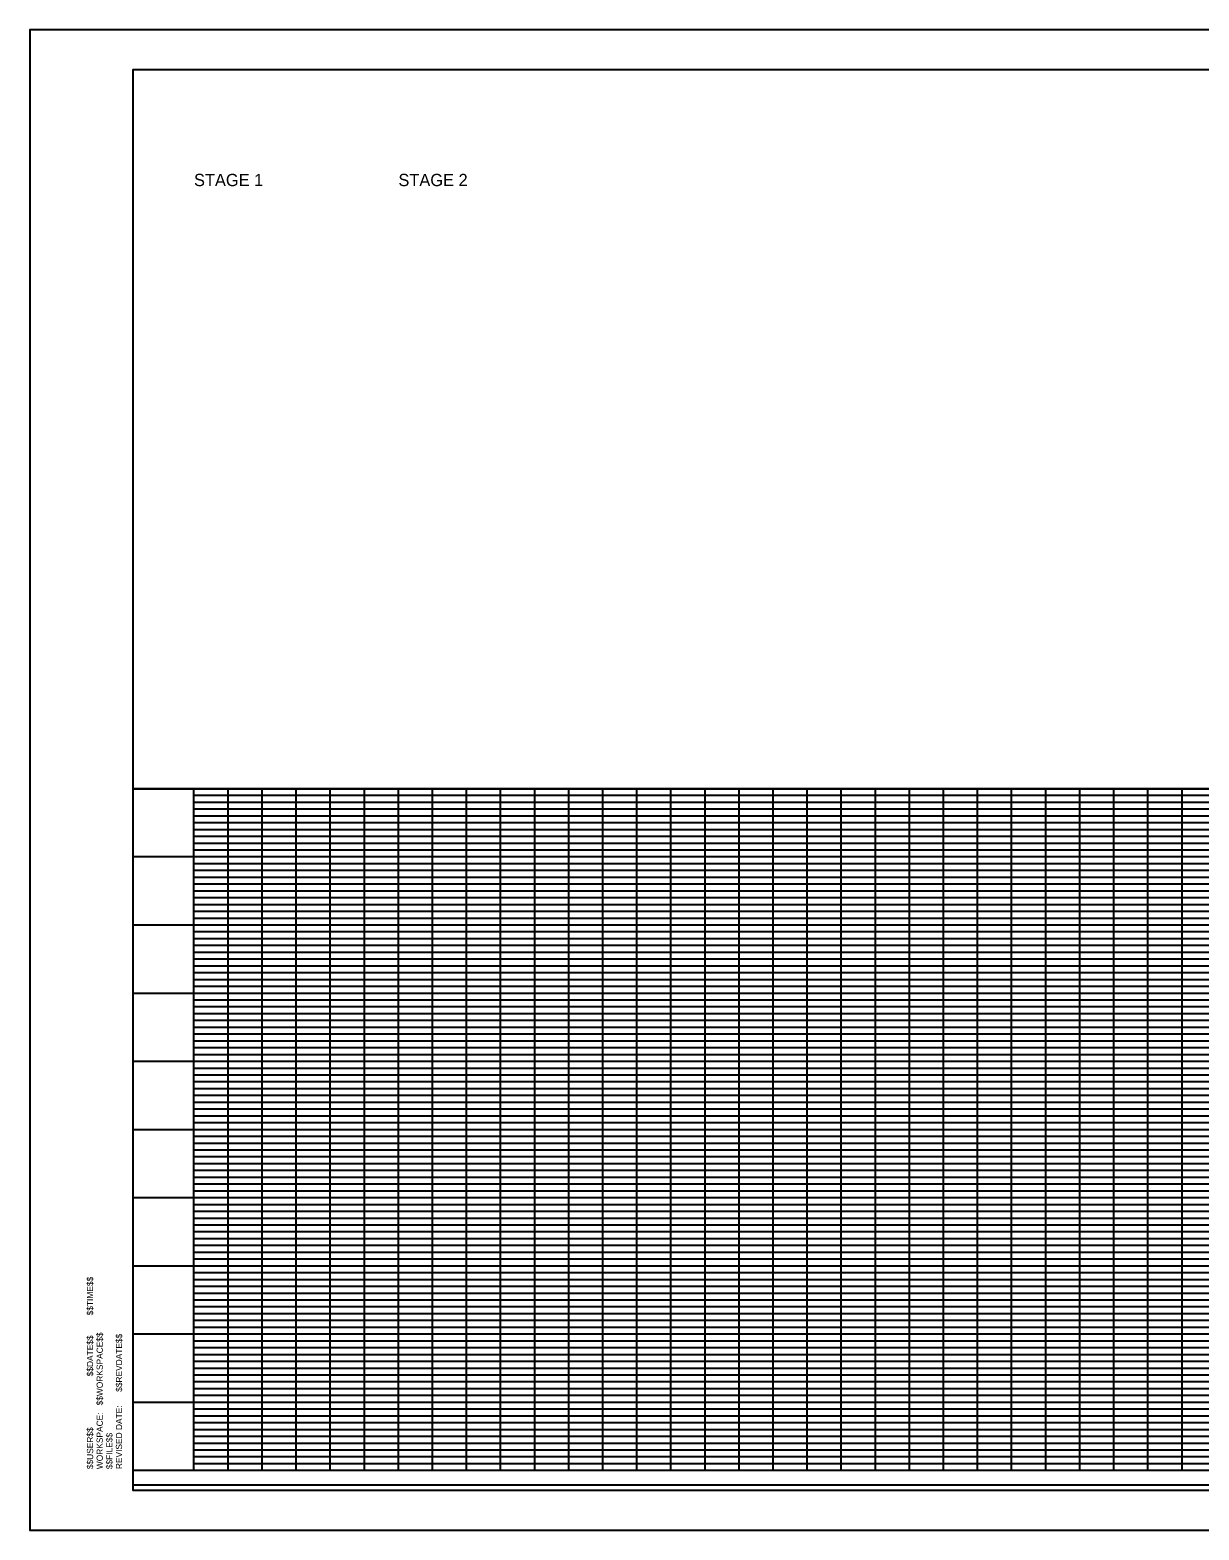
# Model space of a CAD drawing. Extents: x 0 to 1228740, y 0 to 152440.
# Drawn here: x 0 to 17.16, y 0 to 22 of the extents above; entities that cross this region are included whole.
import ezdxf

# ---------------------------------------------------------------- set-up
doc = ezdxf.new("R2010")
doc.units = 0
for name, color, linetype in [('G-TBLK', 7, 'Continuous'), ('R_Border', 7, 'Continuous'), ('R_Grid', 7, 'Continuous'), ('R_No Plot', 7, 'Continuous'), ('R_XS_EARTHWORK_STAGE1', 7, 'Continuous'), ('R_XS_EARTHWORK_STAGE2', 7, 'Continuous')]:
    doc.layers.add(name, color=color, linetype=linetype)

msp = doc.modelspace()

# ---------------------------------------------------------------- linework, layer by layer
at = {"layer": 'R_Border'}
for p, q in [((1.516, 21.423), (33.423, 21.423)), ((1.516, 0.577), (1.516, 21.423)), ((33.423, 0.577), (1.516, 0.577))]:
    msp.add_line(p, q, dxfattribs=at)
msp.add_lwpolyline([(34, 22), (0, 22), (0, 0), (34, 0)], close=True, dxfattribs=at)
at = {"layer": 'R_Grid'}
for p, q in [((33.423, 10.871), (1.516, 10.871)), ((2.407, 0.871), (2.407, 10.871)), ((2.907, 0.871), (2.907, 10.871)), ((3.407, 0.871), (3.407, 10.871)), ((3.907, 0.871), (3.907, 10.871)), ((4.407, 0.871), (4.407, 10.871)), ((4.907, 0.871), (4.907, 10.871)), ((5.407, 0.871), (5.407, 10.871)), ((5.907, 0.871), (5.907, 10.871)), ((6.407, 0.871), (6.407, 10.871)), ((6.907, 0.871), (6.907, 10.871)), ((7.407, 0.871), (7.407, 10.871)), ((7.907, 0.871), (7.907, 10.871)), ((8.407, 0.871), (8.407, 10.871)), ((8.907, 0.871), (8.907, 10.871)), ((9.407, 0.871), (9.407, 10.871)), ((9.907, 0.871), (9.907, 10.871)), ((10.407, 0.871), (10.407, 10.871)), ((10.907, 0.871), (10.907, 10.871)), ((11.407, 0.871), (11.407, 10.871)), ((11.907, 0.871), (11.907, 10.871)), ((12.407, 0.871), (12.407, 10.871)), ((12.907, 0.871), (12.907, 10.871)), ((13.407, 0.871), (13.407, 10.871)), ((13.907, 0.871), (13.907, 10.871)), ((14.407, 0.871), (14.407, 10.871)), ((14.907, 0.871), (14.907, 10.871)), ((15.407, 0.871), (15.407, 10.871)), ((15.907, 0.871), (15.907, 10.871)), ((16.407, 0.871), (16.407, 10.871)), ((16.907, 0.871), (16.907, 10.871)), ((32.407, 10.771), (2.407, 10.771)), ((32.407, 10.671), (2.407, 10.671)), ((32.407, 10.571), (2.407, 10.571)), ((32.407, 10.471), (2.407, 10.471)), ((32.407, 10.371), (2.407, 10.371)), ((32.407, 10.271), (2.407, 10.271)), ((32.407, 10.171), (2.407, 10.171)), ((32.407, 10.071), (2.407, 10.071)), ((32.407, 9.971), (2.407, 9.971)), ((33.423, 9.871), (1.516, 9.871)), ((32.407, 9.771), (2.407, 9.771)), ((32.407, 9.671), (2.407, 9.671)), ((32.407, 9.571), (2.407, 9.571)), ((32.407, 9.471), (2.407, 9.471)), ((32.407, 9.371), (2.407, 9.371)), ((32.407, 9.271), (2.407, 9.271)), ((32.407, 9.171), (2.407, 9.171)), ((32.407, 9.071), (2.407, 9.071)), ((33.423, 8.871), (1.516, 8.871)), ((32.407, 8.971), (2.407, 8.971)), ((32.407, 8.771), (2.407, 8.771)), ((32.407, 8.671), (2.407, 8.671)), ((32.407, 8.571), (2.407, 8.571)), ((32.407, 8.471), (2.407, 8.471)), ((32.407, 8.371), (2.407, 8.371)), ((32.407, 8.271), (2.407, 8.271)), ((32.407, 8.171), (2.407, 8.171)), ((32.407, 8.071), (2.407, 8.071)), ((32.407, 7.971), (2.407, 7.971)), ((33.423, 7.871), (1.516, 7.871)), ((32.407, 7.771), (2.407, 7.771)), ((32.407, 7.671), (2.407, 7.671)), ((32.407, 7.571), (2.407, 7.571)), ((32.407, 7.471), (2.407, 7.471)), ((32.407, 7.371), (2.407, 7.371)), ((32.407, 7.271), (2.407, 7.271)), ((32.407, 7.171), (2.407, 7.171)), ((32.407, 7.071), (2.407, 7.071)), ((33.423, 6.871), (1.516, 6.871)), ((32.407, 6.971), (2.407, 6.971)), ((32.407, 6.771), (2.407, 6.771)), ((32.407, 6.671), (2.407, 6.671)), ((32.407, 6.571), (2.407, 6.571)), ((32.407, 6.471), (2.407, 6.471)), ((32.407, 6.371), (2.407, 6.371)), ((32.407, 6.271), (2.407, 6.271)), ((32.407, 6.171), (2.407, 6.171)), ((32.407, 6.071), (2.407, 6.071)), ((32.407, 5.971), (2.407, 5.971)), ((33.423, 5.871), (1.516, 5.871)), ((32.407, 5.771), (2.407, 5.771)), ((32.407, 5.671), (2.407, 5.671)), ((32.407, 5.571), (2.407, 5.571)), ((32.407, 5.471), (2.407, 5.471)), ((32.407, 5.371), (2.407, 5.371)), ((32.407, 5.271), (2.407, 5.271)), ((32.407, 5.171), (2.407, 5.171)), ((32.407, 5.071), (2.407, 5.071)), ((33.423, 4.871), (1.516, 4.871)), ((32.407, 4.971), (2.407, 4.971)), ((32.407, 4.771), (2.407, 4.771)), ((32.407, 4.671), (2.407, 4.671)), ((32.407, 4.571), (2.407, 4.571)), ((32.407, 4.471), (2.407, 4.471)), ((32.407, 4.371), (2.407, 4.371)), ((32.407, 4.271), (2.407, 4.271)), ((32.407, 4.171), (2.407, 4.171)), ((32.407, 4.071), (2.407, 4.071)), ((32.407, 3.971), (2.407, 3.971)), ((33.423, 3.871), (1.516, 3.871)), ((32.407, 3.771), (2.407, 3.771)), ((32.407, 3.671), (2.407, 3.671)), ((32.407, 3.571), (2.407, 3.571)), ((32.407, 3.471), (2.407, 3.471)), ((32.407, 3.371), (2.407, 3.371)), ((32.407, 3.271), (2.407, 3.271)), ((32.407, 3.171), (2.407, 3.171)), ((33.423, 2.871), (1.516, 2.871)), ((32.407, 3.071), (2.407, 3.071)), ((32.407, 2.971), (2.407, 2.971)), ((32.407, 2.771), (2.407, 2.771)), ((32.407, 2.671), (2.407, 2.671)), ((32.407, 2.571), (2.407, 2.571)), ((32.407, 2.471), (2.407, 2.471)), ((32.407, 2.371), (2.407, 2.371)), ((32.407, 2.271), (2.407, 2.271)), ((32.407, 2.171), (2.407, 2.171)), ((32.407, 2.071), (2.407, 2.071)), ((33.423, 1.871), (1.516, 1.871)), ((32.407, 1.971), (2.407, 1.971)), ((32.407, 1.771), (2.407, 1.771)), ((32.407, 1.671), (2.407, 1.671)), ((32.407, 1.571), (2.407, 1.571)), ((32.407, 1.471), (2.407, 1.471)), ((32.407, 1.371), (2.407, 1.371)), ((32.407, 1.271), (2.407, 1.271)), ((32.407, 1.171), (2.407, 1.171)), ((32.407, 1.071), (2.407, 1.071)), ((32.407, 0.971), (2.407, 0.971)), ((33.423, 0.871), (1.516, 0.871))]:
    msp.add_line(p, q, dxfattribs=at)
at = {"layer": 'R_No Plot'}
for points in [[(33.423, 17.405), (33.423, 10.871), (1.516, 10.871), (1.516, 21.423), (25.197, 21.423), (25.197, 20.435), (28.749, 20.435), (28.749, 20.078), (29.113, 20.078), (29.113, 20.143), (30.667, 20.143)], [(33.423, 17.405), (33.423, 0.657), (1.516, 0.657), (1.516, 21.423), (25.197, 21.423), (25.197, 20.435), (28.749, 20.435), (28.749, 20.078), (29.113, 20.078), (29.113, 20.143), (30.667, 20.143)]]:
    msp.add_lwpolyline(points, dxfattribs=at)
msp.add_lwpolyline([(1.516, 10.871), (33.423, 10.871), (33.423, 0.577), (1.516, 0.577)], close=True, dxfattribs=at)

# ---------------------------------------------------------------- texts
at = {"layer": 'G-TBLK'}
for s, p in [('$$TIME$$', (0.927, 3.148)), ('$$WORKSPACE$$', (1.069, 1.827)), ('$$REVDATE$$', (1.352, 2.026)), ('$$DATE$$', (0.927, 2.254)), ('REVISED DATE:', (1.352, 0.893)), ('WORKSPACE:', (1.069, 0.892)), ('$$USER$$', (0.927, 0.892)), ('$$FILE$$', (1.211, 0.892))]:
    msp.add_text(s, height=0.0918, rotation=90, dxfattribs=at).set_placement(p)
at = {"layer": 'R_XS_EARTHWORK_STAGE1'}
msp.add_text('STAGE 1', height=0.18, dxfattribs=at).set_placement((2.407, 19.71))
at = {"layer": 'R_XS_EARTHWORK_STAGE2'}
msp.add_text('STAGE 2', height=0.18, dxfattribs=at).set_placement((5.407, 19.71))

doc.saveas('drawing.dxf')
